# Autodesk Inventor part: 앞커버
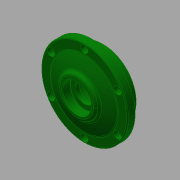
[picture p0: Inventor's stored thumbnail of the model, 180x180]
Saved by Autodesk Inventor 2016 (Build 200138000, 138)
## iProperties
Created: 2016-05
Part Number: 앞커버
Document SubType Name: Modeling
Designer: mduedu
Density: 2.71 g/cm^3
Material: 알루미늄 6061
Appearance: 진녹색
Author: mduedu
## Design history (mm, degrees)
sketch "스케치1"
  geometry: C1 r 35 at (0, 0); C2 r 45 at (0, 0); 1 further point
  constraints: 2 centre point, 2 coincident
  dimensions: "d33" = 90 diameter of C2; "d34" = 70 diameter of C1
extrude "돌출1" new body sketch "스케치1" distance "d0" = 8; taper "d1" = 0 deg
extrude "돌출2" join sketch "스케치1" distance "d2" = 8; taper "d3" = 0 deg; dims "d35" = 12, "d36" = 0
sketch "스케치5"
  geometry: L1 (-45, 8)-(45, 8) reference; L2 (0, 0)-(0, 15); L3 (-45, 0)-(45, 0) reference; L4 (35, 8)-(0, 8); A1 r 91 centre (0, -76) between (35, 8) and (0, 15)
  constraints: 4 end point, 3 point on line, 2 point on circle, 1 centre point, 1 midpoint, 1 perpendicular
  dimensions: "d37" = 35 distance from line of L2 L4.start; "d39" = 7 distance from line of L1 L2.end
revolve "회전2" sketch "스케치5" stored, may be unused: angle "d40" = 90 deg
node "작업 평면1"
sketch "스케치6"
  geometry: C1 r 20 at (0, 0); 1 further point
  constraints: 1 centre point, 1 coincident
  dimensions: "d42" = 40 diameter of C1
extrude "돌출4" join sketch "스케치6" stored distance "d43" = 10; taper "d44" = 0 deg
sketch "스케치4"
  geometry: L1 (0, -12)-(0, 16); L2 (-20, -12)-(-20, 0); L3 (-20, 0)-(-15, 0); L4 (-15, 0)-(-15, 3); L5 (-15, 3)-(-10, 3); L6 (-10, 3)-(-10, 7.5); L7 (-10, 7.5)-(-15, 7.5); L8 (-15, 7.5)-(-15, 16); L9 (35, -12)-(-35, -12) reference; L10 (-20, 16)-(20, 16) reference; 1 further point
  constraints: 16 end point, 6 parallel, 3 point on line, 2 midpoint, 1 perpendicular, 1 vertical
  dimensions: "d15" = 40 diameter of L2 L1; "d16" = 30 diameter of L8 L1; "d18" = 12 distance of L2.start L2.end; "d19" = 3 distance of L3.end L4.end; "d20" = 30 diameter of L4 L1; "d21" = 20 diameter of L6 L1; "d45" = 8.5 distance of L7.end L8.end
revolve "회전1" sketch "스케치4" stored, may be unused: angle "d22" = 90 deg
fillet "모깎기2" dims "d23" = 3
fillet "모깎기3" dims "d24" = 0.3
chamfer "모따기2" distance "d46" = 1; stored, may be unused: second distance "d47" = 2, angle "d48" = 45 deg
fillet "모깎기4" dims "d49" = 3
fillet "모깎기5" dims "d50" = 3
fillet "모깎기6" dims "d51" = 1
sketch "스케치7" dims "d52" = 80
  geometry: C1 r 35.595 at (0, 0) reference; C2 r 44 at (0, 0) reference; 7 further points
  constraints: 2 vertical alignment, 1 coincident, 9 other
  dimensions: "d55" = 360 deg dimension on C1.centre point (0, 40) (derived)
sketch "스케치8"
  geometry: 6 further points
  constraints: 6 other
hole "구멍2" sketch "스케치8" at (-34.641, 20), (-34.641, -20), (0, -40), (34.641, -20), (34.641, 20), (0, 40) diameter "d57" = 4.5; stored, may be unused: countersink angle "d61" = 90 deg, drill point angle "d63" = 0 deg; dims "d58" = 6, "d59" = 8, "d60" = 4.6, "d62" = 8
chamfer "모따기3" distance "d64" = 0.8; stored, may be unused: second distance "d65" = 2, angle "d66" = 30 deg
node "솔리드1"
other parameters: "d41" = 8
